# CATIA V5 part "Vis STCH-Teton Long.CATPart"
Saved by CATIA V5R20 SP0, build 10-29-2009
Part number: Vis STHC-Teton Long M 2.5x5
Material "Acier": density 7860 kg/m3, Young's modulus 2e+11 Pa, Poisson ratio 0.266, thermal expansion 1.17e-05 1/K
Bounding box of the stored display mesh (mm): x -1.25 to 1.25, y -1.25 to 1.25, z 0 to 5
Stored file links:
  C:\travail\CAO\bib catia\vis\Vis STCH-Teton Long.CATPart
  C:\Program Files\Dassault Systemes\B20\win_b64\startup\materials\French\Catalog.CATMaterial
  C:\Program Files\Dassault Systemes\B20\win_b64\reffiles\standard\MetricThickPitch.txt
  C:\travail\CAO\bib catia\vis\vis-HTSC_BP.xls
  C:\travail\CAO\bib catia\vis\vis-HTSC_BC.xls
  C:\travail\CAO\bib catia\vis\vis-HTSC_TL.xls
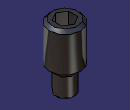
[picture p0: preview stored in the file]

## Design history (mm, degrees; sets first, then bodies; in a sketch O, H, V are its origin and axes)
Parameters
  d = 2.5 mm {design table}
  dp = 1.5 mm {design table}
  t = 2 mm {design table}
  s = 1.3 mm {design table}
  p = 0.45 mm {design table}
  l = 5 mm {design table}
  Designation = "Vis STHC-Teton Long M 2.5x5" {design table}
  dn = "M2,5" {design table}
  tl = 1.5 mm {design table}
Body1 (main body)
  Sketch1 on yz-plane, origin (0, 0, 0), H (0, 1, 0), V (0, 0, 1)
    axis line L1 (0, 0) -> (0, 10.0456)
    line L2 (0, 0) -> (-0.75, 0)
    point P2 (-0.75, 0)
    line L3 (-0.75, 0) -> (-0.75, 1.5)
    line L4 (-1.25, 1.5) -> (-1.25, 5)
    line L5 (-1.25, 5) -> (0, 5)
    point P4 (0, 5)
    line L6 (0, 5) -> (0, 0)
    line L7 (-1.25, 1.5) -> (-0.75, 1.5)
    "Radius" L4 L1 = 1.25 {= d /2}
    distance L2 L5 = 5 {= l}
    "Radius" P2 L1 = 0.75 {= dp /2}
    length L3 = 1.5 {= tl}
    vertical: L1 V, L4 V, L6 V, L3 V
    horizontal: L2 H, L5 H, L7 H
    coincidence: P4 L1
  Shaft1: profile Sketch1, axis Sketch1.L1, angle 360
  Thread1: "M2,5", diameter 2.5, depth 3.5, pitch 0.45, on face of Shaft1 from Sketch1.L4, from face of Shaft1 from Sketch1.L5
  Chamfer1: length 0.225 {= p /2}, angle 45, on edge [face of Shaft1 from Sketch1.L4 | face of Shaft1 from Sketch1.L5]
  Sketch2 on face of Shaft1 from Sketch1.L5, origin (0, 0, 5), H (1, 0, 0), V (0, 1, 0)
    point P1 (0, 0)
    point P2 (0.65, -0.3753)
    point P3 (0.65, 0.3753)
    point P4 (0, 0.7506)
    point P5 (-0.65, 0.3753)
    point P6 (-0.65, -0.3753)
    point P7 (0, -0.7506)
    point P8 (0.65, 0)
    line L1 (0.65, -0.3753) -> (0.65, 0.3753)
    line L2 (0.65, 0.3753) -> (0, 0.7506)
    line L3 (0, 0.7506) -> (-0.65, 0.3753)
    line L4 (-0.65, 0.3753) -> (-0.65, -0.3753)
    line L5 (-0.65, -0.3753) -> (0, -0.7506)
    line L6 (0, -0.7506) -> (0.65, -0.3753)
    construction line L7 (0, 0) -> (0.65, 0)
    construction circle A1 centre (0, 0) radius 0.7506
    construction arc A2 centre (-0.65, -0.3753) radius 0.7506 from (-0.65, 0.3753) to (0, -0.7506) cw
    construction arc A3 centre (0.65, 0.3753) radius 0.7506 from (0, 0.7506) to (0.65, -0.3753) ccw
    distance L4 L1 = 1.3 {= s}
    coincidence: P1 H, A1 P2, A1 P3, A1 P4, A1 P5, A1 P6, A1 P7, A2 P1, A3 P1, P1 O
    horizontal: L7 H
    midpoint: P8 L1
  Pocket1: profile Sketch2, direction (0, 0, -1), length 2 {= t}
  Chamfer2: length 0.5 {= d /2 - dp /2}, angle 45, on edge [face of Shaft1 from Sketch1.L7 | face of Shaft1 from Sketch1.L4]
  Chamfer3: length 0.045 {= p /10}, angle 45, on edge [face of Shaft1 from Sketch1.L2 | face of Shaft1 from Sketch1.L3]
Relations
  Thread1.ThreadDescription = dn
  design table, configuration 2, drives dn, d, p, dp, s, t, tl, l, Designation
